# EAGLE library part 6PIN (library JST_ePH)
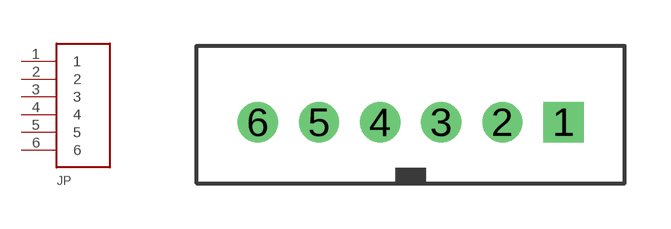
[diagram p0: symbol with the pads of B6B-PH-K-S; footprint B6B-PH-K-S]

Designator prefix JP

## 6PIN  [B6B-PH-K-S]
1  1
2  2
3  3
4  4
5  5
6  6

## Footprint B6B-PH-K-S (pad centres in mm)
drill 0.813 square: 1 5,0
drill 0.813 round: 2 3,0; 3 1,0; 4 -1,0; 5 -3,0; 6 -5,0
